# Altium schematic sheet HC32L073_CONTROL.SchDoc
size A3; CompanyName: 广州立功科技股份有限公司; DocumentNumber: 4; SheetNumber: 4; SheetTotal: 12; PageSetup: Record=PageOptions|CenterHorizontal=True|CenterVertical=True|PrintScale=1.00|XCorrection=1.00|YCorrection=1.00|PrintKind=0|BorderSize=5000000|LeftOffset=0|BottomOffset=0|Orientation=2|PaperLength=1000|PaperWidth=1000|Scale=100|PaperSource=7|PrintQuality=600|MediaType=1|DitherType=10|PaperKind=A4|PrintScaleMode=1; DesignDate: 2020-07-08; SheetName: HC32L073_Control; SheetVersion: Rev.B; SheetDescription: HC32L073各控制功能引脚子图
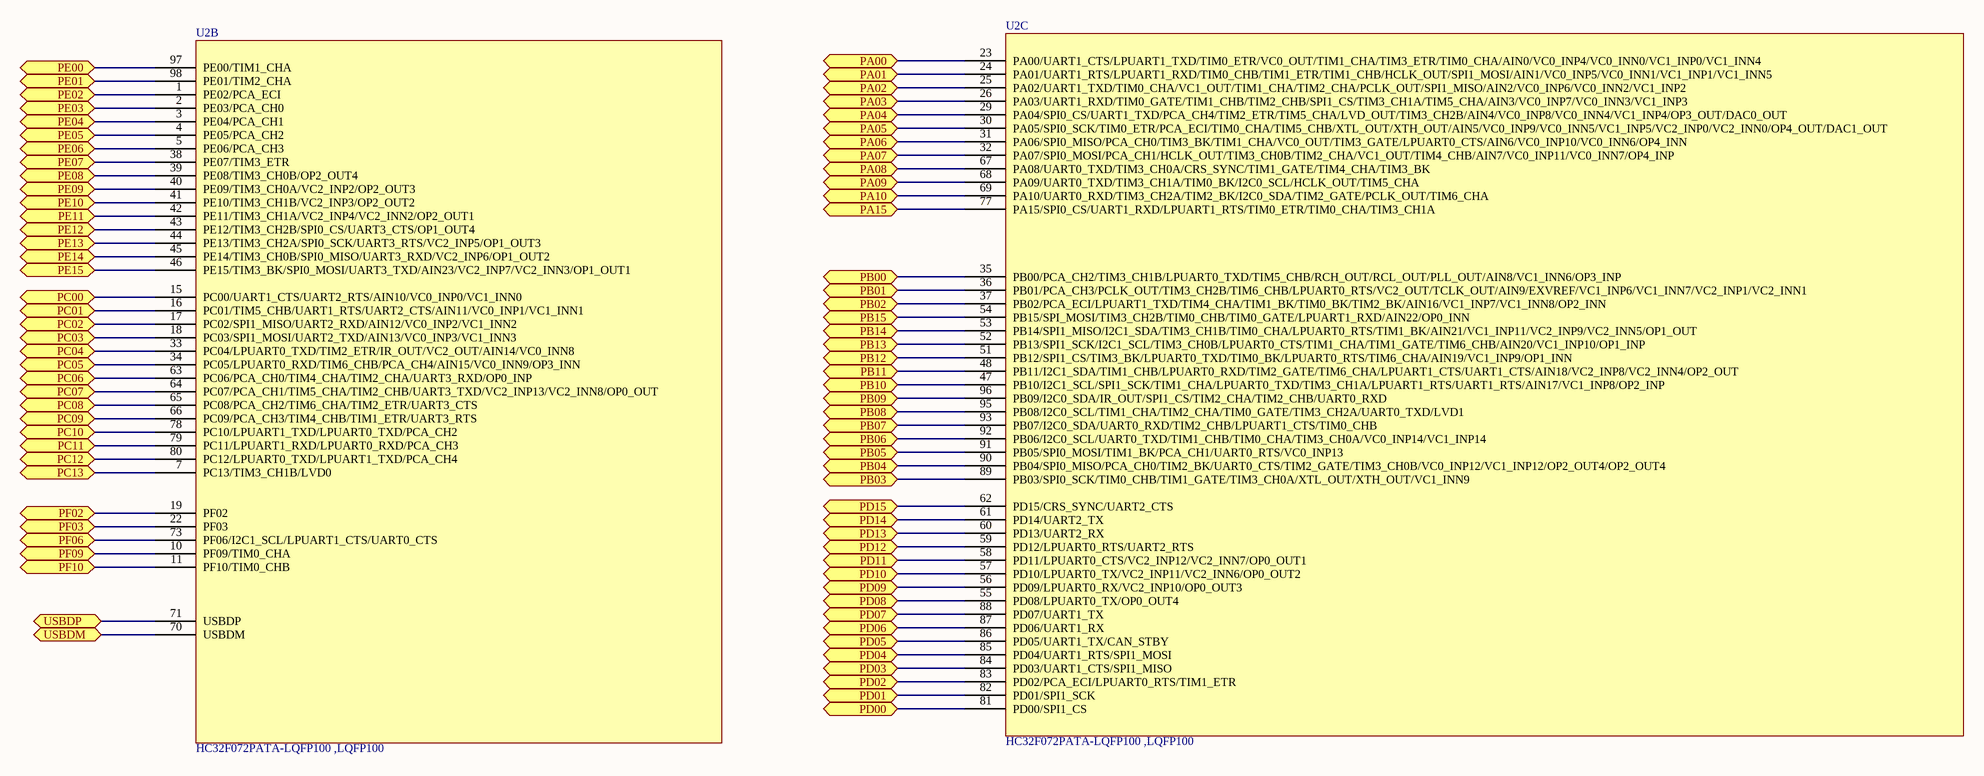
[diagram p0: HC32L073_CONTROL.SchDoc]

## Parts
U2  HC32F072PATA-LQFP100 / ,LQFP100  [QFP50P1600X1600X120-100N]  (parts B,C of 3)

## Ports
PA00, PA01, PA02, PA03, PA04, PA05, PA06, PA07, PA08, PA09, PA10, PA15, PB00, PB01, PB02, PB03, PB04, PB05, PB06, PB07, PB08, PB09, PB10, PB11, PB12, PB13, PB14, PB15, PC00, PC01, PC02, PC03, PC04, PC05, PC06, PC07, PC08, PC09, PC10, PC11, PC12, PC13, PD00, PD01, PD02, PD03, PD04, PD05, PD06, PD07, PD08, PD09, PD10, PD11, PD12, PD13, PD14, PD15, PE00, PE01, PE02, PE03, PE04, PE05, PE06, PE07, PE08, PE09, PE10, PE11, PE12, PE13, PE14, PE15, PF02, PF03, PF06, PF09, PF10, USBDM (bidir), USBDP (bidir)

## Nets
PA00: U2.23(PA00/UART1_CTS/LPUART1_TXD/TIM0_ETR/VC0_OUT/TIM1_CHA/TIM3_ETR/TIM0_CHA/AIN0/VC0_INP4/VC0_INN0/VC1_INP0/VC1_INN4) ; port PA00
PA01: U2.24(PA01/UART1_RTS/LPUART1_RXD/TIM0_CHB/TIM1_ETR/TIM1_CHB/HCLK_OUT/SPI1_MOSI/AIN1/VC0_INP5/VC0_INN1/VC1_INP1/VC1_INN5) ; port PA01
PA02: U2.25(PA02/UART1_TXD/TIM0_CHA/VC1_OUT/TIM1_CHA/TIM2_CHA/PCLK_OUT/SPI1_MISO/AIN2/VC0_INP6/VC0_INN2/VC1_INP2) ; port PA02
PA03: U2.26(PA03/UART1_RXD/TIM0_GATE/TIM1_CHB/TIM2_CHB/SPI1_CS/TIM3_CH1A/TIM5_CHA/AIN3/VC0_INP7/VC0_INN3/VC1_INP3) ; port PA03
PA04: U2.29(PA04/SPI0_CS/UART1_TXD/PCA_CH4/TIM2_ETR/TIM5_CHA/LVD_OUT/TIM3_CH2B/AIN4/VC0_INP8/VC0_INN4/VC1_INP4/OP3_OUT/DAC0_OUT) ; port PA04
PA05: U2.30(PA05/SPI0_SCK/TIM0_ETR/PCA_ECI/TIM0_CHA/TIM5_CHB/XTL_OUT/XTH_OUT/AIN5/VC0_INP9/VC0_INN5/VC1_INP5/VC2_INP0/VC2_INN0/OP4_OUT/DAC1_OUT) ; port PA05
PA06: U2.31(PA06/SPI0_MISO/PCA_CH0/TIM3_BK/TIM1_CHA/VC0_OUT/TIM3_GATE/LPUART0_CTS/AIN6/VC0_INP10/VC0_INN6/OP4_INN) ; port PA06
PA07: U2.32(PA07/SPI0_MOSI/PCA_CH1/HCLK_OUT/TIM3_CH0B/TIM2_CHA/VC1_OUT/TIM4_CHB/AIN7/VC0_INP11/VC0_INN7/OP4_INP) ; port PA07
PA08: U2.67(PA08/UART0_TXD/TIM3_CH0A/CRS_SYNC/TIM1_GATE/TIM4_CHA/TIM3_BK) ; port PA08
PA09: U2.68(PA09/UART0_TXD/TIM3_CH1A/TIM0_BK/I2C0_SCL/HCLK_OUT/TIM5_CHA) ; port PA09
PA10: U2.69(PA10/UART0_RXD/TIM3_CH2A/TIM2_BK/I2C0_SDA/TIM2_GATE/PCLK_OUT/TIM6_CHA) ; port PA10
PA15: U2.77(PA15/SPI0_CS/UART1_RXD/LPUART1_RTS/TIM0_ETR/TIM0_CHA/TIM3_CH1A) ; port PA15
PB00: U2.35(PB00/PCA_CH2/TIM3_CH1B/LPUART0_TXD/TIM5_CHB/RCH_OUT/RCL_OUT/PLL_OUT/AIN8/VC1_INN6/OP3_INP) ; port PB00
PB01: U2.36(PB01/PCA_CH3/PCLK_OUT/TIM3_CH2B/TIM6_CHB/LPUART0_RTS/VC2_OUT/TCLK_OUT/AIN9/EXVREF/VC1_INP6/VC1_INN7/VC2_INP1/VC2_INN1) ; port PB01
PB02: U2.37(PB02/PCA_ECI/LPUART1_TXD/TIM4_CHA/TIM1_BK/TIM0_BK/TIM2_BK/AIN16/VC1_INP7/VC1_INN8/OP2_INN) ; port PB02
PB03: U2.89(PB03/SPI0_SCK/TIM0_CHB/TIM1_GATE/TIM3_CH0A/XTL_OUT/XTH_OUT/VC1_INN9) ; port PB03
PB04: U2.90(PB04/SPI0_MISO/PCA_CH0/TIM2_BK/UART0_CTS/TIM2_GATE/TIM3_CH0B/VC0_INP12/VC1_INP12/OP2_OUT4/OP2_OUT4) ; port PB04
PB05: U2.91(PB05/SPI0_MOSI/TIM1_BK/PCA_CH1/UART0_RTS/VC0_INP13) ; port PB05
PB06: U2.92(PB06/I2C0_SCL/UART0_TXD/TIM1_CHB/TIM0_CHA/TIM3_CH0A/VC0_INP14/VC1_INP14) ; port PB06
PB07: U2.93(PB07/I2C0_SDA/UART0_RXD/TIM2_CHB/LPUART1_CTS/TIM0_CHB) ; port PB07
PB08: U2.95(PB08/I2C0_SCL/TIM1_CHA/TIM2_CHA/TIM0_GATE/TIM3_CH2A/UART0_TXD/LVD1) ; port PB08
PB09: U2.96(PB09/I2C0_SDA/IR_OUT/SPI1_CS/TIM2_CHA/TIM2_CHB/UART0_RXD) ; port PB09
PB10: U2.47(PB10/I2C1_SCL/SPI1_SCK/TIM1_CHA/LPUART0_TXD/TIM3_CH1A/LPUART1_RTS/UART1_RTS/AIN17/VC1_INP8/OP2_INP) ; port PB10
PB11: U2.48(PB11/I2C1_SDA/TIM1_CHB/LPUART0_RXD/TIM2_GATE/TIM6_CHA/LPUART1_CTS/UART1_CTS/AIN18/VC2_INP8/VC2_INN4/OP2_OUT) ; port PB11
PB12: U2.51(PB12/SPI1_CS/TIM3_BK/LPUART0_TXD/TIM0_BK/LPUART0_RTS/TIM6_CHA/AIN19/VC1_INP9/OP1_INN) ; port PB12
PB13: U2.52(PB13/SPI1_SCK/I2C1_SCL/TIM3_CH0B/LPUART0_CTS/TIM1_CHA/TIM1_GATE/TIM6_CHB/AIN20/VC1_INP10/OP1_INP) ; port PB13
PB14: U2.53(PB14/SPI1_MISO/I2C1_SDA/TIM3_CH1B/TIM0_CHA/LPUART0_RTS/TIM1_BK/AIN21/VC1_INP11/VC2_INP9/VC2_INN5/OP1_OUT) ; port PB14
PB15: U2.54(PB15/SPI_MOSI/TIM3_CH2B/TIM0_CHB/TIM0_GATE/LPUART1_RXD/AIN22/OP0_INN) ; port PB15
PC00: U2.15(PC00/UART1_CTS/UART2_RTS/AIN10/VC0_INP0/VC1_INN0) ; port PC00
PC01: U2.16(PC01/TIM5_CHB/UART1_RTS/UART2_CTS/AIN11/VC0_INP1/VC1_INN1) ; port PC01
PC02: U2.17(PC02/SPI1_MISO/UART2_RXD/AIN12/VC0_INP2/VC1_INN2) ; port PC02
PC03: U2.18(PC03/SPI1_MOSI/UART2_TXD/AIN13/VC0_INP3/VC1_INN3) ; port PC03
PC04: U2.33(PC04/LPUART0_TXD/TIM2_ETR/IR_OUT/VC2_OUT/AIN14/VC0_INN8) ; port PC04
PC05: U2.34(PC05/LPUART0_RXD/TIM6_CHB/PCA_CH4/AIN15/VC0_INN9/OP3_INN) ; port PC05
PC06: U2.63(PC06/PCA_CH0/TIM4_CHA/TIM2_CHA/UART3_RXD/OP0_INP) ; port PC06
PC07: U2.64(PC07/PCA_CH1/TIM5_CHA/TIM2_CHB/UART3_TXD/VC2_INP13/VC2_INN8/OP0_OUT) ; port PC07
PC08: U2.65(PC08/PCA_CH2/TIM6_CHA/TIM2_ETR/UART3_CTS) ; port PC08
PC09: U2.66(PC09/PCA_CH3/TIM4_CHB/TIM1_ETR/UART3_RTS) ; port PC09
PC10: U2.78(PC10/LPUART1_TXD/LPUART0_TXD/PCA_CH2) ; port PC10
PC11: U2.79(PC11/LPUART1_RXD/LPUART0_RXD/PCA_CH3) ; port PC11
PC12: U2.80(PC12/LPUART0_TXD/LPUART1_TXD/PCA_CH4) ; port PC12
PC13: U2.7(PC13/TIM3_CH1B/LVD0) ; port PC13
PD00: U2.81(PD00/SPI1_CS) ; port PD00
PD01: U2.82(PD01/SPI1_SCK) ; port PD01
PD02: U2.83(PD02/PCA_ECI/LPUART0_RTS/TIM1_ETR) ; port PD02
PD03: U2.84(PD03/UART1_CTS/SPI1_MISO) ; port PD03
PD04: U2.85(PD04/UART1_RTS/SPI1_MOSI) ; port PD04
PD05: U2.86(PD05/UART1_TX/CAN_STBY) ; port PD05
PD06: U2.87(PD06/UART1_RX) ; port PD06
PD07: U2.88(PD07/UART1_TX) ; port PD07
PD08: U2.55(PD08/LPUART0_TX/OP0_OUT4) ; port PD08
PD09: U2.56(PD09/LPUART0_RX/VC2_INP10/OP0_OUT3) ; port PD09
PD10: U2.57(PD10/LPUART0_TX/VC2_INP11/VC2_INN6/OP0_OUT2) ; port PD10
PD11: U2.58(PD11/LPUART0_CTS/VC2_INP12/VC2_INN7/OP0_OUT1) ; port PD11
PD12: U2.59(PD12/LPUART0_RTS/UART2_RTS) ; port PD12
PD13: U2.60(PD13/UART2_RX) ; port PD13
PD14: U2.61(PD14/UART2_TX) ; port PD14
PD15: U2.62(PD15/CRS_SYNC/UART2_CTS) ; port PD15
PE00: U2.97(PE00/TIM1_CHA) ; port PE00
PE01: U2.98(PE01/TIM2_CHA) ; port PE01
PE02: U2.1(PE02/PCA_ECI) ; port PE02
PE03: U2.2(PE03/PCA_CH0) ; port PE03
PE04: U2.3(PE04/PCA_CH1) ; port PE04
PE05: U2.4(PE05/PCA_CH2) ; port PE05
PE06: U2.5(PE06/PCA_CH3) ; port PE06
PE07: U2.38(PE07/TIM3_ETR) ; port PE07
PE08: U2.39(PE08/TIM3_CH0B/OP2_OUT4) ; port PE08
PE09: U2.40(PE09/TIM3_CH0A/VC2_INP2/OP2_OUT3) ; port PE09
PE10: U2.41(PE10/TIM3_CH1B/VC2_INP3/OP2_OUT2) ; port PE10
PE11: U2.42(PE11/TIM3_CH1A/VC2_INP4/VC2_INN2/OP2_OUT1) ; port PE11
PE12: U2.43(PE12/TIM3_CH2B/SPI0_CS/UART3_CTS/OP1_OUT4) ; port PE12
PE13: U2.44(PE13/TIM3_CH2A/SPI0_SCK/UART3_RTS/VC2_INP5/OP1_OUT3) ; port PE13
PE14: U2.45(PE14/TIM3_CH0B/SPI0_MISO/UART3_RXD/VC2_INP6/OP1_OUT2) ; port PE14
PE15: U2.46(PE15/TIM3_BK/SPI0_MOSI/UART3_TXD/AIN23/VC2_INP7/VC2_INN3/OP1_OUT1) ; port PE15
PF02: U2.19(PF02) ; port PF02
PF03: U2.22(PF03) ; port PF03
PF06: U2.73(PF06/I2C1_SCL/LPUART1_CTS/UART0_CTS) ; port PF06
PF09: U2.10(PF09/TIM0_CHA) ; port PF09
PF10: U2.11(PF10/TIM0_CHB) ; port PF10
USBDM: U2.70(USBDM) ; port USBDM
USBDP: U2.71(USBDP) ; port USBDP

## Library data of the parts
U2 = 08.20.00249: HC32F072PATA-LQFP100 / ,LQFP100,华大HDSC; 名称: 集成电路; 贴片和直插: SMT; PCB备注: 200929hcj; 器件优选方案: 待导入物料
